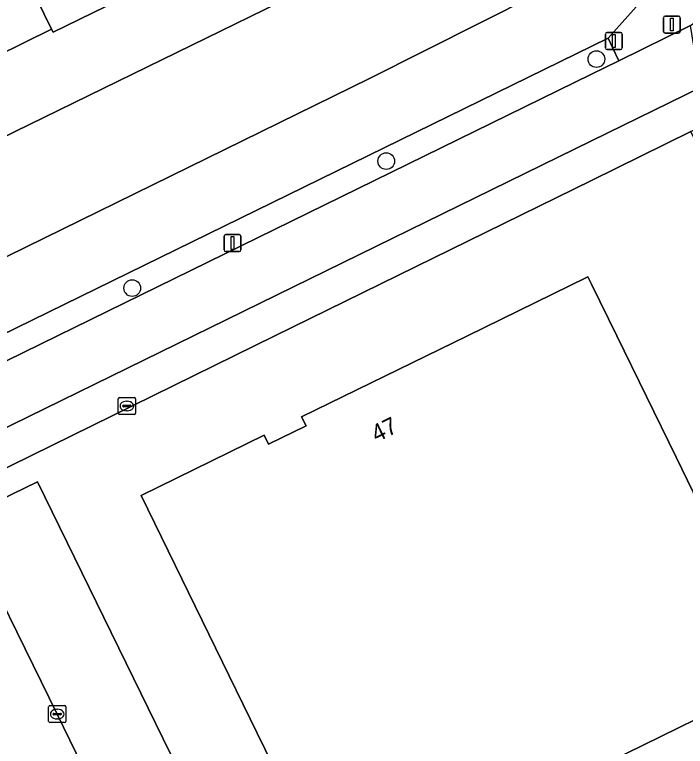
# Model space of a CAD drawing. Extents: x 160455 to 162082, y 388339 to 389736.
# Drawn here: x 160966.19 to 161005.5, y 388725.95 to 388768.82 of the extents above; entities that cross this region are included whole.
import ezdxf

# ---------------------------------------------------------------- set-up
doc = ezdxf.new("R2010")
doc.units = 0
for name, color, linetype in [('IMGEO_Berm_groen', 7, 'Continuous'), ('IMGEO_Boom', 7, 'Continuous'), ('IMGEO_Erf', 7, 'Continuous'), ('IMGEO_Fietspad_gesloten', 7, 'Continuous'), ('IMGEO_Groenvoorziening', 7, 'Continuous'), ('IMGEO_Haag', 7, 'Continuous'), ('IMGEO_Kolk', 7, 'Continuous'), ('IMGEO_Lichtmast', 7, 'Continuous'), ('IMGEO_Oever', 7, 'Continuous'), ('IMGEO_Pand', 7, 'Continuous'), ('IMGEO_Pand_nummerreeks', 7, 'Continuous'), ('IMGEO_Parkeervlak_open', 7, 'Continuous'), ('IMGEO_Rijbaan_lokaal_open', 7, 'Continuous'), ('IMGEO_Rioolput', 7, 'Continuous'), ('IMGEO_Verkeersbordpaal', 7, 'Continuous'), ('IMGEO_Voetpad_open', 7, 'Continuous'), ('IMGEO_Waterloop', 7, 'Continuous')]:
    doc.layers.add(name, color=color, linetype=linetype)

msp = doc.modelspace()

# ---------------------------------------------------------------- linework, layer by layer
at = {"layer": 'IMGEO_Berm_groen'}
msp.add_lwpolyline([(161006.759, 388768.862), (161006.221, 388769.932), (161005.782, 388769.718), (161005.511, 388770.302), (161005.645, 388770.381), (161004.923, 388771.881), (161000.979, 388767.447), (161001.239, 388766.89), (161001.6, 388766.116), (161005.803, 388768.175)], close=True, dxfattribs=at)
at = {"layer": 'IMGEO_Boom'}
for centre in [(161000.287, 388766.212), (160987.972, 388760.235), (160973.081, 388752.797)]:
    msp.add_circle(centre, 0.489, dxfattribs=at)
at = {"layer": 'IMGEO_Erf'}
msp.add_lwpolyline([(160961.835, 388764.759), (160968.352, 388767.962), (160966.64, 388771.457), (160969.727, 388772.968), (160971.437, 388769.478), (160971.723, 388769.618), (160971.166, 388770.788), (160971.277, 388770.846), (160966.804, 388779.925), (160962.46, 388788.776)], dxfattribs=at)
for points in [[(161020.621, 388731.678), (161006.266, 388761.054), (161005.821, 388761.965), (161000, 388759.109), (160981.436, 388750), (160962.382, 388740.651), (160963.059, 388739.275), (160967.518, 388741.446), (160982.232, 388711.367), (160983.598, 388711.346), (160986.381, 388705.418), (161000, 388705.227), (161020.646, 388704.937), (161020.64, 388710.846), (161020.64, 388711.063)], [(160994.446, 388721.812), (160994.186, 388722.342), (160992.005, 388721.275), (160992.265, 388720.746), (160985.061, 388717.206), (160985.007, 388717.316), (160980.412, 388726.718), (160978.766, 388730.087), (160973.602, 388740.653), (160980.818, 388744.18), (160981.077, 388743.649), (160983.269, 388744.72), (160983.009, 388745.25), (160992.728, 388750), (160999.714, 388753.414), (160999.791, 388753.452), (161000, 388753.025), (161001.478, 388750), (161004.954, 388742.889), (161006.623, 388739.473), (161011.231, 388730.046), (161000, 388724.537)]]:
    msp.add_lwpolyline(points, close=True, dxfattribs=at)
at = {"layer": 'IMGEO_Fietspad_gesloten'}
for points in [[(160976.671, 388750), (161000, 388761.421), (161006.396, 388764.552), (161005.803, 388768.175), (161001.6, 388766.116), (161000, 388765.333), (160968.696, 388750), (160830.802, 388682.457), (160825.311, 388679.157), (160825.396, 388678.948)], [(160835.236, 388680.785), (160877.263, 388701.324), (160886.716, 388705.962), (160976.671, 388750)]]:
    msp.add_lwpolyline(points, dxfattribs=at)
at = {"layer": 'IMGEO_Groenvoorziening'}
for points in [[(160985.165, 388771.24), (160998.756, 388778.042), (160998.487, 388778.589), (160984.612, 388771.79), (160982.973, 388775.146), (160971.723, 388769.618), (160971.437, 388769.478), (160971.525, 388769.298), (160968.438, 388767.786), (160968.352, 388767.962), (160961.835, 388764.759), (160961.98, 388764.463), (160958.917, 388762.963), (160958.774, 388763.255), (160958.502, 388763.122), (160958.569, 388762.984), (160955.512, 388761.487), (160955.447, 388761.62), (160949.905, 388758.897), (160950.96, 388756.743), (160948.021, 388755.303), (160948.921, 388753.525)], [(160968.696, 388750), (161000, 388765.333), (161001.6, 388766.116), (161001.239, 388766.89), (161000.979, 388767.447), (160965.347, 388750), (160778.313, 388658.421), (160776.807, 388656.846), (160777.453, 388655.571), (160825.396, 388678.948), (160825.311, 388679.157), (160830.802, 388682.457)]]:
    msp.add_lwpolyline(points, close=True, dxfattribs=at)
at = {"layer": 'IMGEO_Haag'}
msp.add_lwpolyline([(160968.696, 388750), (161000, 388765.333), (161001.6, 388766.116), (161001.239, 388766.89), (161000.979, 388767.447), (160965.347, 388750), (160778.313, 388658.421), (160776.807, 388656.846), (160777.453, 388655.571), (160825.396, 388678.948), (160825.311, 388679.157), (160830.802, 388682.457)], close=True, dxfattribs=at)
at = {"layer": 'IMGEO_Kolk'}
for p, q in [((160968.182, 388727.413), (160968.182, 388728.265)), ((160968.257, 388728.339), (160969.109, 388728.339)), ((160969.183, 388728.265), (160969.183, 388727.413)), ((160968.441, 388727.833), (160968.441, 388727.845)), ((160968.879, 388727.796), (160968.481, 388727.796)), ((160968.484, 388727.882), (160968.882, 388727.882)), ((160968.67, 388728.119), (160968.695, 388728.119)), ((160968.925, 388727.845), (160968.925, 388727.833)), ((160968.693, 388727.559), (160968.668, 388727.559)), ((160969.109, 388727.339), (160968.257, 388727.339))]:
    msp.add_line(p, q, dxfattribs=at)
for points in [[(160968.182, 388727.413), (160968.182, 388728.265)], [(160968.257, 388728.339), (160969.109, 388728.339)], [(160969.183, 388728.265), (160969.183, 388727.413)], [(160969.109, 388727.339), (160968.257, 388727.339)]]:
    msp.add_lwpolyline(points, dxfattribs=at)
for centre, radius, start, end in [((160968.259, 388728.263), 0.0765, 91.552, 178.448), ((160968.259, 388728.263), 0.0765, 91.552, 178.448), ((160969.107, 388728.263), 0.0765, 1.552, 88.448), ((160969.107, 388728.263), 0.0765, 1.552, 88.448), ((160968.481, 388727.842), 0.0403, 85.8775, 175.7526), ((160968.478, 388727.832), 0.0366, 178.938, 274.7102), ((160968.882, 388727.839), 0.043, 264.8664, 352.4533), ((160968.886, 388727.844), 0.0386, 1.7309, 96.639), ((160968.259, 388727.415), 0.0765, 181.552, 268.448), ((160968.259, 388727.415), 0.0765, 181.552, 268.448), ((160969.107, 388727.415), 0.0765, 271.552, 358.448), ((160969.107, 388727.415), 0.0765, 271.552, 358.448)]:
    msp.add_arc(centre, radius, start, end, dxfattribs=at)
for centre, major_axis, ratio, start_param, end_param in [((160968.669, 388727.839), (-0.387, 0.002), 0.722429, 4.712389, 7.853982), ((160968.694, 388727.839), (-0.39, 0.002), 0.717154, 1.570796, 4.712389)]:
    msp.add_ellipse(centre, major_axis=major_axis, ratio=ratio, start_param=start_param, end_param=end_param, dxfattribs=at)
at = {"layer": 'IMGEO_Lichtmast'}
for p, q in [((161004.21, 388767.836), (161004.21, 388768.636)), ((161004.21, 388768.636), (161004.21, 388767.836)), ((161004.31, 388768.736), (161005.1, 388768.736)), ((161005.1, 388768.736), (161004.31, 388768.736)), ((161005.2, 388768.636), (161005.2, 388767.836)), ((161005.2, 388767.836), (161005.2, 388768.636)), ((161005.1, 388767.736), (161004.31, 388767.736)), ((161004.31, 388767.736), (161005.1, 388767.736)), ((160978.461, 388755.035), (160978.461, 388755.835)), ((160978.461, 388755.835), (160978.461, 388755.035)), ((160978.561, 388755.935), (160979.351, 388755.935)), ((160979.351, 388755.935), (160978.561, 388755.935)), ((160979.451, 388755.835), (160979.451, 388755.035)), ((160979.451, 388755.035), (160979.451, 388755.835)), ((160979.351, 388754.935), (160978.561, 388754.935)), ((160978.561, 388754.935), (160979.351, 388754.935))]:
    msp.add_line(p, q, dxfattribs=at)
for points in [[(161004.63, 388768.611), (161004.78, 388768.611), (161004.78, 388767.861), (161004.63, 388767.861), (161004.63, 388768.611)], [(160978.881, 388755.81), (160979.031, 388755.81), (160979.031, 388755.06), (160978.881, 388755.06), (160978.881, 388755.81)]]:
    msp.add_lwpolyline(points, dxfattribs=at)
for centre, start, end in [((161004.31, 388768.636), 90, 180), ((161004.31, 388768.636), 90, 180), ((161005.1, 388768.636), 0, 90), ((161005.1, 388768.636), 360, 90), ((161004.31, 388767.836), 180, 270), ((161004.31, 388767.836), 180, 270), ((161005.1, 388767.836), 270, 0), ((161005.1, 388767.836), 270, 0), ((160978.561, 388755.835), 90, 180), ((160978.561, 388755.835), 90, 180), ((160979.351, 388755.835), 0, 90), ((160979.351, 388755.835), 360, 90), ((160978.561, 388755.035), 180, 270), ((160978.561, 388755.035), 180, 270), ((160979.351, 388755.035), 270, 0), ((160979.351, 388755.035), 270, 0)]:
    msp.add_arc(centre, 0.1, start, end, dxfattribs=at)
at = {"layer": 'IMGEO_Oever'}
msp.add_lwpolyline([(160965.347, 388750), (161000.979, 388767.447), (161004.923, 388771.881), (161004.47, 388772.822), (161004.366, 388772.775), (161004.045, 388773.679), (161000, 388771.638), (160986.989, 388765.073), (160956.23, 388750), (160783.435, 388665.323), (160769.08, 388658.493), (160770.196, 388656.176), (160776.807, 388656.846), (160778.313, 388658.421)], close=True, dxfattribs=at)
at = {"layer": 'IMGEO_Pand'}
for points in [[(160966.64, 388771.457), (160968.352, 388767.962), (160968.438, 388767.786), (160971.525, 388769.298), (160971.437, 388769.478), (160969.727, 388772.968)], [(160983.009, 388745.25), (160983.269, 388744.72), (160981.077, 388743.649), (160980.818, 388744.18), (160973.602, 388740.653), (160978.766, 388730.087), (160980.412, 388726.718), (160985.007, 388717.316), (160985.061, 388717.206), (160992.265, 388720.746), (160992.005, 388721.275), (160994.186, 388722.342), (160994.446, 388721.812), (161000, 388724.537), (161011.231, 388730.046), (161006.623, 388739.473), (161004.954, 388742.889), (161001.478, 388750), (161000, 388753.025), (160999.791, 388753.452), (160999.714, 388753.414), (160992.728, 388750)]]:
    msp.add_lwpolyline(points, close=True, dxfattribs=at)
at = {"layer": 'IMGEO_Parkeervlak_open'}
msp.add_lwpolyline([(160982.232, 388711.367), (160967.518, 388741.446), (160963.059, 388739.275), (160968.684, 388727.84), (160972.373, 388720.249), (160976.723, 388711.453)], close=True, dxfattribs=at)
at = {"layer": 'IMGEO_Rijbaan_lokaal_open'}
msp.add_lwpolyline([(160963.059, 388739.275), (160962.382, 388740.651), (160957.1, 388738.085), (160972.792, 388705.905), (160972.937, 388705.607), (160977.941, 388705.537), (160986.381, 388705.418), (160983.598, 388711.346), (160982.232, 388711.367), (160976.723, 388711.453), (160972.373, 388720.249), (160968.684, 388727.84)], close=True, dxfattribs=at)
at = {"layer": 'IMGEO_Rioolput'}
for p, q in [((160972.264, 388745.461), (160972.264, 388746.313)), ((160972.339, 388746.387), (160973.191, 388746.387)), ((160973.265, 388746.313), (160973.265, 388745.461)), ((160972.523, 388745.881), (160972.523, 388745.893)), ((160972.961, 388745.844), (160972.563, 388745.844)), ((160972.566, 388745.93), (160972.964, 388745.93)), ((160972.752, 388746.167), (160972.777, 388746.167)), ((160973.007, 388745.893), (160973.007, 388745.881)), ((160973.191, 388745.387), (160972.339, 388745.387)), ((160972.775, 388745.607), (160972.75, 388745.607))]:
    msp.add_line(p, q, dxfattribs=at)
for points in [[(160972.264, 388745.461), (160972.264, 388746.313)], [(160972.339, 388746.387), (160973.191, 388746.387)], [(160973.265, 388746.313), (160973.265, 388745.461)], [(160973.191, 388745.387), (160972.339, 388745.387)]]:
    msp.add_lwpolyline(points, dxfattribs=at)
for centre, radius, start, end in [((160972.341, 388746.311), 0.0765, 91.552, 178.448), ((160972.341, 388746.311), 0.0765, 91.552, 178.448), ((160973.189, 388746.311), 0.0765, 1.552, 88.448), ((160973.189, 388746.311), 0.0765, 1.552, 88.448), ((160972.563, 388745.89), 0.0403, 85.8775, 175.7526), ((160972.56, 388745.88), 0.0366, 178.938, 274.7102), ((160972.964, 388745.887), 0.043, 264.8664, 352.4533), ((160972.968, 388745.892), 0.0386, 1.7309, 96.639), ((160972.341, 388745.463), 0.0765, 181.552, 268.448), ((160972.341, 388745.463), 0.0765, 181.552, 268.448), ((160973.189, 388745.463), 0.0765, 271.552, 358.448), ((160973.189, 388745.463), 0.0765, 271.552, 358.448)]:
    msp.add_arc(centre, radius, start, end, dxfattribs=at)
for centre, major_axis, ratio, start_param, end_param in [((160972.751, 388745.887), (-0.387, 0.002), 0.722429, 4.712389, 7.853982), ((160972.776, 388745.887), (-0.39, 0.002), 0.717154, 1.570796, 4.712389)]:
    msp.add_ellipse(centre, major_axis=major_axis, ratio=ratio, start_param=start_param, end_param=end_param, dxfattribs=at)
at = {"layer": 'IMGEO_Verkeersbordpaal'}
for p, q in [((161000.811, 388766.874), (161000.811, 388767.674)), ((161000.811, 388767.674), (161000.811, 388766.874)), ((161000.911, 388767.774), (161001.701, 388767.774)), ((161001.701, 388767.774), (161000.911, 388767.774)), ((161001.801, 388767.674), (161001.801, 388766.874)), ((161001.801, 388766.874), (161001.801, 388767.674)), ((161001.701, 388766.774), (161000.911, 388766.774)), ((161000.911, 388766.774), (161001.701, 388766.774))]:
    msp.add_line(p, q, dxfattribs=at)
msp.add_lwpolyline([(161001.231, 388767.649), (161001.381, 388767.649), (161001.381, 388766.899), (161001.231, 388766.899), (161001.231, 388767.649)], dxfattribs=at)
for centre, start, end in [((161000.911, 388767.674), 90, 180), ((161000.911, 388767.674), 90, 180), ((161001.701, 388767.674), 0, 90), ((161001.701, 388767.674), 360, 90), ((161000.911, 388766.874), 180, 270), ((161000.911, 388766.874), 180, 270), ((161001.701, 388766.874), 270, 0), ((161001.701, 388766.874), 270, 0)]:
    msp.add_arc(centre, 0.1, start, end, dxfattribs=at)
at = {"layer": 'IMGEO_Voetpad_open'}
msp.add_lwpolyline([(160957.1, 388738.085), (160962.382, 388740.651), (160981.436, 388750), (161000, 388759.109), (161005.821, 388761.965), (161007.303, 388762.692), (161006.396, 388764.552), (161000, 388761.421), (160976.671, 388750), (160886.716, 388705.962)], dxfattribs=at)
at = {"layer": 'IMGEO_Waterloop'}
msp.add_lwpolyline([(160956.23, 388750), (160986.989, 388765.073), (161000, 388771.638), (161004.045, 388773.679), (161001.348, 388779.301), (161000, 388778.665), (160998.756, 388778.042), (160985.165, 388771.24), (160948.921, 388753.525), (160941.708, 388750), (160766.298, 388664.267), (160769.08, 388658.493), (160783.435, 388665.323)], close=True, dxfattribs=at)

# ---------------------------------------------------------------- texts
at = {"layer": 'IMGEO_Pand_nummerreeks'}
msp.add_text('47', height=1, rotation=26.0455, dxfattribs=at).set_placement((160987.395, 388743.742))

doc.saveas('drawing.dxf')
